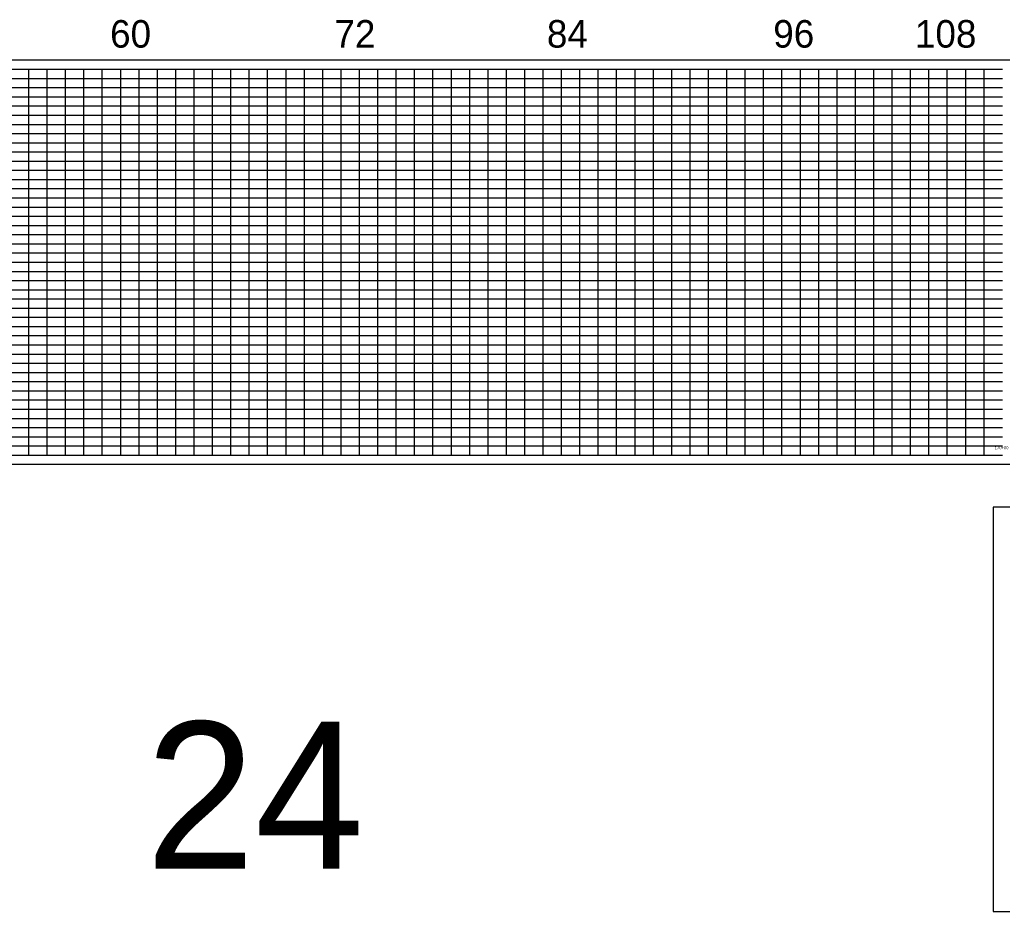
# Model space of a CAD drawing. Extents: x 1873632 to 1926512, y 813126 to 836257.
# Drawn here: x 1891688 to 1894363, y 824367 to 826793 of the extents above; entities that cross this region are included whole.
import ezdxf

# ---------------------------------------------------------------- set-up
doc = ezdxf.new("R2010")
doc.units = 0
for name, color, linetype in [('RD_DDB_StaTX', 7, 'Continuous'), ('RD_PD_WallFill', 7, 'Continuous'), ('RD_SHT_IplotShp', 7, 'Continuous'), ('RD_Sketch8', 7, 'Continuous')]:
    doc.layers.add(name, color=color, linetype=linetype)

msp = doc.modelspace()

# ---------------------------------------------------------------- linework, layer by layer
at = {"layer": 'RD_PD_WallFill'}
for p, q in [((1889013.1, 826658.1), (1894363.1, 826658.1)), ((1891713.1, 825608.1), (1891713.1, 826658.1)), ((1891713.1, 825608.1), (1891713.1, 826658.1)), ((1891763.1, 825608.1), (1891763.1, 826658.1)), ((1891763.1, 825608.1), (1891763.1, 826658.1)), ((1891813.1, 825608.1), (1891813.1, 826658.1)), ((1891813.1, 825608.1), (1891813.1, 826658.1)), ((1891863.1, 825608.1), (1891863.1, 826658.1)), ((1891863.1, 825608.1), (1891863.1, 826658.1)), ((1891913.1, 825608.1), (1891913.1, 826658.1)), ((1891913.1, 825608.1), (1891913.1, 826658.1)), ((1891963.1, 825608.1), (1891963.1, 826658.1)), ((1891963.1, 825608.1), (1891963.1, 826658.1)), ((1892013.1, 825608.1), (1892013.1, 826658.1)), ((1892013.1, 825608.1), (1892013.1, 826658.1)), ((1892063.1, 825608.1), (1892063.1, 826658.1)), ((1892063.1, 825608.1), (1892063.1, 826658.1)), ((1892113.1, 825608.1), (1892113.1, 826658.1)), ((1892113.1, 825608.1), (1892113.1, 826658.1)), ((1892163.1, 825608.1), (1892163.1, 826658.1)), ((1892163.1, 825608.1), (1892163.1, 826658.1)), ((1892213.1, 825608.1), (1892213.1, 826658.1)), ((1892213.1, 825608.1), (1892213.1, 826658.1)), ((1892263.1, 825608.1), (1892263.1, 826658.1)), ((1892263.1, 825608.1), (1892263.1, 826658.1)), ((1892313.1, 825608.1), (1892313.1, 826658.1)), ((1892313.1, 825608.1), (1892313.1, 826658.1)), ((1892363.1, 825608.1), (1892363.1, 826658.1)), ((1892363.1, 825608.1), (1892363.1, 826658.1)), ((1892413.1, 825608.1), (1892413.1, 826658.1)), ((1892413.1, 825608.1), (1892413.1, 826658.1)), ((1892463.1, 825608.1), (1892463.1, 826658.1)), ((1892463.1, 825608.1), (1892463.1, 826658.1)), ((1892513.1, 825608.1), (1892513.1, 826658.1)), ((1892513.1, 825608.1), (1892513.1, 826658.1)), ((1892563.1, 825608.1), (1892563.1, 826658.1)), ((1892563.1, 825608.1), (1892563.1, 826658.1)), ((1892613.1, 825608.1), (1892613.1, 826658.1)), ((1892613.1, 825608.1), (1892613.1, 826658.1)), ((1892663.1, 825608.1), (1892663.1, 826658.1)), ((1892663.1, 825608.1), (1892663.1, 826658.1)), ((1892713.1, 825608.1), (1892713.1, 826658.1)), ((1892713.1, 825608.1), (1892713.1, 826658.1)), ((1892763.1, 825608.1), (1892763.1, 826658.1)), ((1892763.1, 825608.1), (1892763.1, 826658.1)), ((1892813.1, 825608.1), (1892813.1, 826658.1)), ((1892813.1, 825608.1), (1892813.1, 826658.1)), ((1892863.1, 825608.1), (1892863.1, 826658.1)), ((1892863.1, 825608.1), (1892863.1, 826658.1)), ((1892913.1, 825608.1), (1892913.1, 826658.1)), ((1892913.1, 825608.1), (1892913.1, 826658.1)), ((1892963.1, 825608.1), (1892963.1, 826658.1)), ((1892963.1, 825608.1), (1892963.1, 826658.1)), ((1893013.1, 825608.1), (1893013.1, 826658.1)), ((1893013.1, 825608.1), (1893013.1, 826658.1)), ((1893063.1, 825608.1), (1893063.1, 826658.1)), ((1893063.1, 825608.1), (1893063.1, 826658.1)), ((1893113.1, 825608.1), (1893113.1, 826658.1)), ((1893113.1, 825608.1), (1893113.1, 826658.1)), ((1893163.1, 825608.1), (1893163.1, 826658.1)), ((1893163.1, 825608.1), (1893163.1, 826658.1)), ((1893213.1, 825608.1), (1893213.1, 826658.1)), ((1893213.1, 825608.1), (1893213.1, 826658.1)), ((1893263.1, 825608.1), (1893263.1, 826658.1)), ((1893263.1, 825608.1), (1893263.1, 826658.1)), ((1893313.1, 825608.1), (1893313.1, 826658.1)), ((1893313.1, 825608.1), (1893313.1, 826658.1)), ((1893363.1, 825608.1), (1893363.1, 826658.1)), ((1893363.1, 825608.1), (1893363.1, 826658.1)), ((1893413.1, 825608.1), (1893413.1, 826658.1)), ((1893413.1, 825608.1), (1893413.1, 826658.1)), ((1893463.1, 825608.1), (1893463.1, 826658.1)), ((1893463.1, 825608.1), (1893463.1, 826658.1)), ((1893513.1, 825608.1), (1893513.1, 826658.1)), ((1893513.1, 825608.1), (1893513.1, 826658.1)), ((1893563.1, 825608.1), (1893563.1, 826658.1)), ((1893563.1, 825608.1), (1893563.1, 826658.1)), ((1893613.1, 825608.1), (1893613.1, 826658.1)), ((1893613.1, 825608.1), (1893613.1, 826658.1)), ((1893663.1, 825608.1), (1893663.1, 826658.1)), ((1893663.1, 825608.1), (1893663.1, 826658.1)), ((1893713.1, 825608.1), (1893713.1, 826658.1)), ((1893713.1, 825608.1), (1893713.1, 826658.1)), ((1893763.1, 825608.1), (1893763.1, 826658.1)), ((1893763.1, 825608.1), (1893763.1, 826658.1)), ((1893813.1, 825608.1), (1893813.1, 826658.1)), ((1893813.1, 825608.1), (1893813.1, 826658.1)), ((1893863.1, 825608.1), (1893863.1, 826658.1)), ((1893863.1, 825608.1), (1893863.1, 826658.1)), ((1893913.1, 825608.1), (1893913.1, 826658.1)), ((1893913.1, 825608.1), (1893913.1, 826658.1)), ((1893963.1, 825608.1), (1893963.1, 826658.1)), ((1893963.1, 825608.1), (1893963.1, 826658.1)), ((1894013.1, 825608.1), (1894013.1, 826658.1)), ((1894013.1, 825608.1), (1894013.1, 826658.1)), ((1894063.1, 825608.1), (1894063.1, 826658.1)), ((1894063.1, 825608.1), (1894063.1, 826658.1)), ((1894113.1, 825608.1), (1894113.1, 826658.1)), ((1894113.1, 825608.1), (1894113.1, 826658.1)), ((1894163.1, 825608.1), (1894163.1, 826658.1)), ((1894163.1, 825608.1), (1894163.1, 826658.1)), ((1894213.1, 825608.1), (1894213.1, 826658.1)), ((1894213.1, 825608.1), (1894213.1, 826658.1)), ((1894263.1, 825608.1), (1894263.1, 826658.1)), ((1894263.1, 825608.1), (1894263.1, 826658.1)), ((1894313.1, 825608.1), (1894313.1, 826658.1)), ((1894313.1, 825608.1), (1894313.1, 826658.1)), ((1889463.1, 826633.1), (1894363.1, 826633.1)), ((1889463.1, 826633.1), (1894363.1, 826633.1)), ((1889463.1, 826608.1), (1894363.1, 826608.1)), ((1889463.1, 826583.1), (1894363.1, 826583.1)), ((1889463.1, 826558.1), (1894363.1, 826558.1)), ((1889463.1, 826533.1), (1894363.1, 826533.1)), ((1889013.1, 826508.1), (1894363.1, 826508.1)), ((1889013.1, 826483.1), (1894363.1, 826483.1)), ((1889013.1, 826458.1), (1894363.1, 826458.1)), ((1889013.1, 826433.1), (1894363.1, 826433.1)), ((1889013.1, 826408.1), (1894363.1, 826408.1)), ((1889013.1, 826383.1), (1894363.1, 826383.1)), ((1889013.1, 826358.1), (1894363.1, 826358.1)), ((1889013.1, 826333.1), (1894363.1, 826333.1)), ((1889013.1, 826308.1), (1894363.1, 826308.1)), ((1889013.1, 826283.1), (1894363.1, 826283.1)), ((1889013.1, 826258.1), (1894363.1, 826258.1)), ((1889013.1, 826233.1), (1894363.1, 826233.1)), ((1889013.1, 826208.1), (1894363.1, 826208.1)), ((1889013.1, 826183.1), (1894363.1, 826183.1)), ((1889013.1, 826158.1), (1894363.1, 826158.1)), ((1889013.1, 826133.1), (1894363.1, 826133.1)), ((1889013.1, 826108.1), (1894363.1, 826108.1)), ((1889013.1, 826083.1), (1894363.1, 826083.1)), ((1889013.1, 826058.1), (1894363.1, 826058.1)), ((1889013.1, 826033.1), (1894363.1, 826033.1)), ((1889013.1, 826008.1), (1894363.1, 826008.1)), ((1889013.1, 825983.1), (1894363.1, 825983.1)), ((1889013.1, 825958.1), (1894363.1, 825958.1)), ((1889013.1, 825933.1), (1894363.1, 825933.1)), ((1889013.1, 825908.1), (1894363.1, 825908.1)), ((1889013.1, 825883.1), (1894363.1, 825883.1)), ((1889013.1, 825858.1), (1894363.1, 825858.1)), ((1889013.1, 825833.1), (1894363.1, 825833.1)), ((1889013.1, 825808.1), (1894363.1, 825808.1)), ((1889013.1, 825783.1), (1894363.1, 825783.1)), ((1889013.1, 825758.1), (1894363.1, 825758.1)), ((1889013.1, 825733.1), (1894363.1, 825733.1)), ((1889013.1, 825708.1), (1894363.1, 825708.1)), ((1889013.1, 825683.1), (1894363.1, 825683.1)), ((1889013.1, 825658.1), (1894363.1, 825658.1)), ((1889013.1, 825633.1), (1894363.1, 825633.1)), ((1889013.1, 825608.1), (1894363.1, 825608.1)), ((1889013.1, 825608.1), (1894363.1, 825608.1))]:
    msp.add_line(p, q, dxfattribs=at)
at = {"layer": 'RD_SHT_IplotShp'}
for points in [[(1888988.1, 825583.1), (1894388.1, 825583.1), (1894388.1, 826683.1), (1888988.1, 826683.1)], [(1894338.1, 824366.6), (1899738.1, 824366.6), (1899738.1, 825466.6), (1894338.1, 825466.6)]]:
    msp.add_lwpolyline(points, close=True, dxfattribs=at)

# ---------------------------------------------------------------- texts
at = {"layer": 'RD_DDB_StaTX'}
msp.add_text('170+00', height=8, dxfattribs=at).set_placement((1894342.2, 825624.1))
at = {"layer": 'RD_PD_WallFill'}
for s, p in [('60', (1891934.3, 826716.8)), ('60', (1891934.3, 826716.8)), ('72', (1892544.9, 826716.8)), ('72', (1892544.9, 826716.8)), ('84', (1893123.2, 826716.8)), ('84', (1893123.2, 826716.8)), ('96', (1893739.3, 826716.8)), ('96', (1893739.3, 826716.8)), ('108', (1894125, 826716.8))]:
    msp.add_text(s, height=75, dxfattribs=at).set_placement(p)
at = {"layer": 'RD_Sketch8'}
msp.add_text('24', height=400, dxfattribs=at).set_placement((1892031, 824482.5))

doc.saveas('drawing.dxf')
